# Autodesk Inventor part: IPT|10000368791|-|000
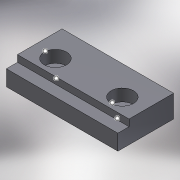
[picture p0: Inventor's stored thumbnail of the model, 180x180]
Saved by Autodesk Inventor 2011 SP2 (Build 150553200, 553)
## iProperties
Created: 2012-11
Part Number: IPT|10000368791|-|000
Material: S235JRG2
Document SubType Name: Modeling
Designer: SCHALLA
Density: 7.85 g/cm^3
MatBom2.0.1.: PS!Inventor!PV!15.0  SP: 2!AVMa!2!AVMi!0!AVBu!0
DCAG_GPT_3D_DESCRIPTION_GER: NICHT_GEFÜLLT
Title: NICHT_GEFÜLLT
Author: SCHALLA
Revision Number: -
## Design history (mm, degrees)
sketch "Skizze2"
  geometry: L1 (12.5, -5)-(-12.5, -5); L2 (-12.5, -5)-(-12.5, 2); L3 (-12.5, 2)-(-7.5, 2); L4 (-7.5, 2)-(-7.5, 5); L5 (-7.5, 5)-(12.5, 5); L6 (12.5, 5)-(12.5, -5); L7 (-12.5, -5)-(12.5, 5); 2 further points
  constraints: 14 end point, 3 perpendicular, 2 horizontal, 1 coincident, 1 midpoint, 1 parallel
  dimensions: "d2" = 10 distance between parallel lines of L5 L1; "d3" = 3 distance between parallel lines of L5 L3; "d4" = 25 distance of L1.start L1.end; "d5" = 20 distance of L4.end L5.end
extrude "Grundkoerper" new body sketch "Skizze2" stored distance "d6" = 50; taper "d7" = 0 deg
sketch "Skizze3"
  geometry: L1 (20, 50)-(20, 0) reference; 3 further points
  constraints: 1 vertical alignment
  dimensions: "d8" = 30 distance of point (7, 10) point (7, 40); "d9" = 13 distance from line of point (7, 40) L1; "d10" = 15 vertical distance of point (7.5, 25) point (7, 40) (= 0.5 x d8)
hole "Hole1" sketch "Skizze3" at (7, 10), (7, 40) diameter "d11" = 5.5; stored, may be unused: countersink angle "d15" = 90 deg, drill point angle "d17" = 118 deg; dims "d12" = 6, "d13" = 10, "d14" = 5.4, "d16" = 8
node "Volumenkörper2"
other parameters: "d18" = 0, "d19" = 0, "d20" = 0, "d21" = 0
